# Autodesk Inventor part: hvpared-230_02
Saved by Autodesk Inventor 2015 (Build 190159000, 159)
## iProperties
Created: 2020-08
Part Number: hvpared-230_02
Checked By: TraceParts S.A.
Material: Generic
Catalog Web Link: www.traceparts.com
Document SubType Name: Modeling
Designer: TraceParts
Density: 1 g/cm^3
Appearance: Default
Company: TraceParts S.A.
Author: TraceParts
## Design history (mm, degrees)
feature "hvpared-230_02.ipt"
body "Solid1"
